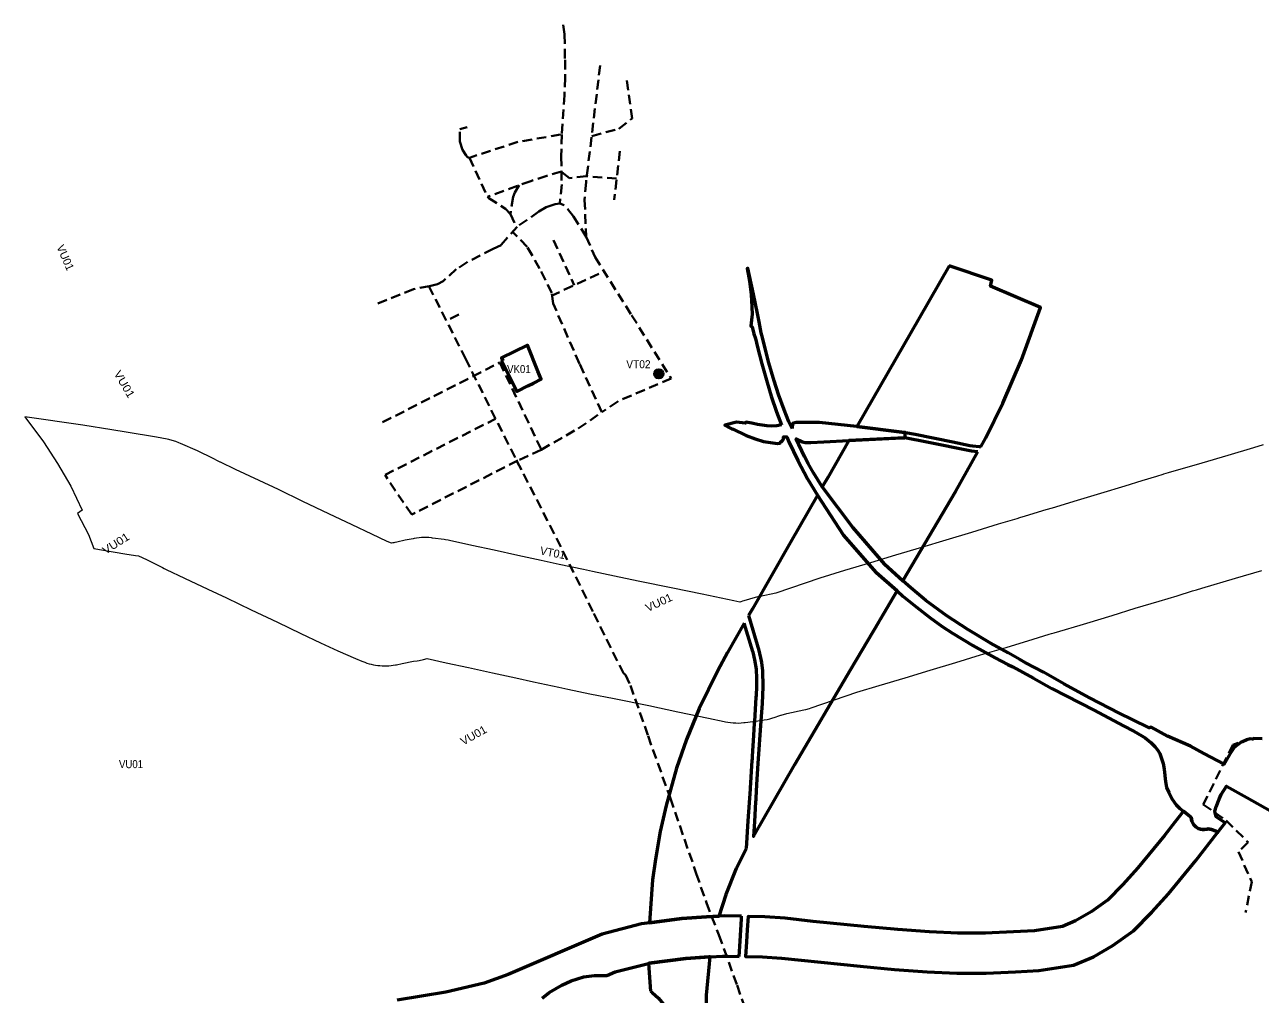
# Model space of a CAD drawing. Extents: x -650145 to -642675, y -1074338 to -1066724.
# Drawn here: x -649600 to -646512, y -1069147 to -1066724 of the extents above; entities that cross this region are included whole.
import ezdxf

# ---------------------------------------------------------------- set-up
doc = ezdxf.new("R2010")
doc.units = 0
doc.header["$LTSCALE"] = 8
doc.linetypes.add('MEDIUM_DASHED', pattern=[4.5, 3, -1.5])
for name, color, linetype in [('1', 7, 'Continuous'), ('17', 7, 'Continuous'), ('2', 7, 'Continuous')]:
    doc.layers.add(name, color=color, linetype=linetype)
for name, color, linetype, lineweight in [('12', 7, 'MEDIUM_DASHED', 40), ('15', 7, 'Continuous', 13), ('44', 7, 'Continuous', 53), ('45', 7, 'Continuous', 53)]:
    doc.layers.add(name, color=color, linetype=linetype, lineweight=lineweight)

msp = doc.modelspace()

# ---------------------------------------------------------------- hatches: boundary and pattern name
at = {"layer": '15'}
msp.add_hatch(color=256, dxfattribs=at).paths.add_polyline_path([(-648003.776, -1067596.576, 1), (-648027.301, -1067596.576, 1)])

# ---------------------------------------------------------------- linework, layer by layer
at = {"layer": '12'}
for p, q in [((-648112.923, -1067040.185), (-648126.71, -1067161.68)), ((-648278.693, -1067262.163), (-648226.9, -1067375.166)), ((-648165.273, -1067346.538), (-648282.098, -1067400.808)), ((-648515.199, -1067448.468), (-648546.557, -1067463.228))]:
    msp.add_line(p, q, dxfattribs=at)
for points in [[(-648254.111, -1066724.115), (-648250.825, -1066748.213), (-648249.73, -1066811.744), (-648248.971, -1066855.783), (-648251.033, -1066899.78), (-648258.055, -1066998.612), (-648259.37, -1067053.379), (-648258.055, -1067123.482), (-648262.874, -1067170.801), (-648274.266, -1067172.334), (-648297.049, -1067180.221), (-648315.013, -1067191.174), (-648369.562, -1067228.854), (-648409.651, -1067274.641), (-648429.367, -1067284.499), (-648494.475, -1067317.053), (-648521.596, -1067335.324), (-648554.018, -1067364.678), (-648568.696, -1067372.565), (-648588.85, -1067377.165), (-648628.502, -1067385.052), (-648726.865, -1067424.267)], [(-648161.945, -1066826.336), (-648197.181, -1067117.94), (-648200.826, -1067161.68), (-648196.766, -1067253.967), (-648228.816, -1067203.221), (-648251.518, -1067175.177), (-648262.874, -1067170.801)], [(-648182.601, -1067002.513), (-648115.19, -1066984.032), (-648082.101, -1066958.613), (-648096.04, -1066857.23)], [(-648488.5, -1067056.457), (-648493.497, -1067055.091), (-648496.863, -1067051.153), (-648505.895, -1067036.526), (-648512.776, -1067015.949), (-648512.582, -1066985.375), (-648494.033, -1066979.937)], [(-648261.097, -1066998.621), (-648367.277, -1067016.878), (-648488.5, -1067056.457), (-648443.711, -1067154.017)], [(-648258.664, -1067091.005), (-648295.035, -1067101.44), (-648334.906, -1067114.73), (-648443.711, -1067154.017), (-648440.351, -1067157.668), (-648398.143, -1067183.811), (-648386.313, -1067197.539), (-648370.813, -1067230.283)], [(-648120.689, -1067108.619), (-648196.172, -1067102.839), (-648238.811, -1067107.157), (-648258.654, -1067091.57)], [(-648364.124, -1067125.28), (-648375.197, -1067142.997), (-648379.372, -1067154.48), (-648386.313, -1067197.539)], [(-648196.766, -1067253.967), (-648174.431, -1067304.992), (-648083.383, -1067449.946), (-647984.432, -1067607.856), (-648117.975, -1067665.279), (-648157.356, -1067692.42), (-648213.545, -1067571.236), (-648279.612, -1067420.693), (-648282.899, -1067394.398), (-648313.139, -1067332.931), (-648344.694, -1067279.025), (-648380.675, -1067241.546)], [(-648589.741, -1067377.342), (-648498.624, -1067558.559), (-648369.855, -1067814.661), (-648270.948, -1068007.281), (-648177.599, -1068195.293), (-648103.97, -1068344.741), (-648098.419, -1068348.539), (-648086.184, -1068375.018), (-648042.175, -1068501.421), (-647986.295, -1068657.442), (-647921.652, -1068844.799), (-647896.268, -1068918.371), (-647865.117, -1068998.629), (-647819.537, -1069124.409), (-647801.818, -1069175.256)], [(-648705.527, -1067717.518), (-648412.884, -1067568.459), (-648309.025, -1067786), (-648368.053, -1067813.183), (-648633.004, -1067948.289), (-648699.635, -1067849.093), (-648423.205, -1067708.555)], [(-648309.025, -1067786), (-648216.797, -1067733.386), (-648157.356, -1067692.42)], [(-646567.712, -1068518.211), (-646580.293, -1068523.244), (-646654.473, -1068672.619), (-646597.568, -1068712.249), (-646542.696, -1068767.122), (-646566.575, -1068791.001), (-646533.55, -1068865.689), (-646548.767, -1068942.794)]]:
    msp.add_lwpolyline(points, dxfattribs=at)
at = {"layer": '15'}
for points in [[(-649382.683, -1067736.41), (-649454.621, -1067724.642), (-649600.146, -1067704.069)], [(-649600.146, -1067704.069), (-649553.44, -1067766.28), (-649518.25, -1067820.92), (-649485.13, -1067877.09), (-649456.24, -1067937.25), (-649467.89, -1067945.1), (-649440.52, -1067998.08), (-649427.146, -1068033.129), (-649350.073, -1068045.91)], [(-646504.961, -1067774.022), (-646529.365, -1067781.499), (-646593.13, -1067800.524), (-646658.06, -1067819.479), (-646742.053, -1067843.994), (-646753.887, -1067847.445), (-646755.382, -1067847.819), (-646771.25, -1067852.794), (-646807.854, -1067864.206), (-646850.892, -1067877.156), (-646911.586, -1067895.218), (-646969.855, -1067913.144), (-647032.093, -1067931.929), (-647048.173, -1067936.726), (-647099.576, -1067952.077), (-647114.132, -1067956.487), (-647120.451, -1067958.402), (-647126.241, -1067960.149), (-647166.751, -1067972.422), (-647233.528, -1067992.581), (-647298.314, -1068011.911), (-647358.997, -1068030.632), (-647423.612, -1068049.375), (-647486.376, -1068068.781), (-647550.936, -1068088.002), (-647612.779, -1068106.747), (-647722.769, -1068144.312), (-647762.416, -1068152.578), (-647765.408, -1068153.202), (-647771.336, -1068154.692), (-647774.267, -1068155.557), (-647802.757, -1068163.967), (-647805.815, -1068164.87), (-647810.703, -1068166.542), (-647812.571, -1068166.788), (-647827.9, -1068163.347), (-647906.909, -1068147.095), (-647980.144, -1068131.782), (-648067.22, -1068114.186), (-648126.418, -1068101.998), (-648181.06, -1068090.497), (-648203.256, -1068085.824), (-648264.087, -1068072.869), (-648309.141, -1068062.702), (-648367.602, -1068050.464), (-648426.568, -1068037.47), (-648482.748, -1068025.289), (-648538.58, -1068012.914), (-648541.779, -1068012.205), (-648548.234, -1068011.067), (-648551.482, -1068010.64), (-648580.682, -1068006.8), (-648583.733, -1068006.399), (-648589.862, -1068005.847), (-648596.008, -1068005.548), (-648602.162, -1068005.5), (-648608.312, -1068005.705), (-648614.449, -1068006.163), (-648620.561, -1068006.871), (-648626.64, -1068007.83), (-648629.657, -1068008.433), (-648649.671, -1068012.436), (-648670.491, -1068016.914), (-648675.031, -1068017.89), (-648677.625, -1068018.618), (-648680.26, -1068018.992), (-648683.7, -1068019.718), (-648693.991, -1068015.264), (-648732.758, -1067996.958), (-648781.439, -1067974.125), (-648839.635, -1067946.226), (-648905.118, -1067915.461), (-648966.216, -1067885.853), (-649013.828, -1067863.231), (-649073.136, -1067835.331), (-649111.1, -1067817.381), (-649111.919, -1067816.904), (-649116.61, -1067814.593), (-649129.493, -1067808.246), (-649168.436, -1067789.027), (-649210.538, -1067770.325), (-649214.568, -1067768.535), (-649222.823, -1067765.435), (-649231.246, -1067762.826), (-649239.808, -1067760.715), (-649244.144, -1067759.913), (-649270.928, -1067754.958), (-649346.551, -1067742.368), (-649382.683, -1067736.41)], [(-649350.073, -1068045.91), (-649322.852, -1068050.442), (-649316.134, -1068051.685), (-649295.764, -1068060.733), (-649262.167, -1068077.314), (-649255.583, -1068080.557), (-649251.7, -1068082.747), (-649246.836, -1068085.047), (-649201.104, -1068106.669), (-649142.052, -1068134.449), (-649096.004, -1068156.327), (-649034.322, -1068186.219), (-648968.265, -1068217.254), (-648909.981, -1068245.195), (-648860.502, -1068268.402), (-648817.649, -1068288.636), (-648773.793, -1068307.617), (-648757.876, -1068314.337), (-648755.322, -1068315.416), (-648750.136, -1068317.382), (-648744.882, -1068319.156), (-648739.566, -1068320.735), (-648734.195, -1068322.115), (-648728.777, -1068323.297), (-648723.319, -1068324.277), (-648717.828, -1068325.055), (-648712.312, -1068325.63), (-648706.779, -1068326), (-648701.236, -1068326.166), (-648695.69, -1068326.126), (-648690.15, -1068325.882), (-648684.623, -1068325.433), (-648679.116, -1068324.78), (-648673.637, -1068323.924), (-648670.915, -1068323.395), (-648657.024, -1068320.696), (-648628.18, -1068314.608), (-648619.413, -1068313.366), (-648614.155, -1068312.621), (-648603.771, -1068310.391), (-648594.694, -1068307.758), (-648546.992, -1068318.331), (-648490.632, -1068330.55)], [(-648127.18, -1068408.134), (-648040.556, -1068425.638), (-647967.831, -1068440.845), (-647890.98, -1068456.653), (-647852.243, -1068465.348), (-647849.022, -1068466.071), (-647842.522, -1068467.232), (-647835.978, -1068468.107), (-647829.402, -1068468.692), (-647822.806, -1068468.988), (-647816.203, -1068468.993), (-647809.607, -1068468.707), (-647803.03, -1068468.132), (-647799.757, -1068467.7), (-647755.597, -1068461.87), (-647751.962, -1068461.39), (-647744.747, -1068460.076), (-647737.604, -1068458.41), (-647730.552, -1068456.398), (-647727.079, -1068455.221), (-647712.829, -1068450.391), (-647710.163, -1068449.487), (-647709.521, -1068449.242), (-647695.198, -1068445.014), (-647652.454, -1068436.102), (-647647.917, -1068435.156), (-647638.976, -1068432.708), (-647634.59, -1068431.21), (-647520.761, -1068392.333), (-647464.624, -1068375.318), (-647399.264, -1068355.859), (-647337.508, -1068336.765), (-647272.983, -1068318.048), (-647211.206, -1068298.989), (-647147.292, -1068279.919), (-647079.909, -1068259.578), (-647039.419, -1068247.311), (-647033.609, -1068245.558), (-647027.128, -1068243.593), (-647013.164, -1068239.363), (-646962.367, -1068224.194), (-646945.867, -1068219.271), (-646882.405, -1068200.116), (-646824.694, -1068182.362), (-646764.888, -1068164.564), (-646719.986, -1068151.054), (-646681.73, -1068139.126), (-646671.337, -1068135.868), (-646658.027, -1068131.986), (-646574, -1068107.461), (-646508.21, -1068088.256)], [(-648490.632, -1068330.55), (-648430.618, -1068343.776), (-648372.899, -1068355.858), (-648328.353, -1068365.911), (-648265.404, -1068379.316), (-648242.86, -1068384.063), (-648187.562, -1068395.702), (-648127.18, -1068408.134)]]:
    msp.add_lwpolyline(points, dxfattribs=at)
at = {"layer": '15', "lineweight": 35}
msp.add_circle((-648015.538, -1067596.576), 11.762, dxfattribs=at)
at = {"layer": '44'}
msp.add_line((-648038.596, -1068968.281), (-647958.168, -1068957.73), dxfattribs=at)
for points in [[(-647289.924, -1067326.309), (-647364.024, -1067455.561), (-647520.145, -1067727.879), (-647408.2, -1067742.37), (-647398.74, -1067743.15)], [(-647210.537, -1067778.594), (-647198.088, -1067756.5), (-647155.592, -1067670.17), (-647108.971, -1067561.55), (-647061.252, -1067430.908), (-647185.93, -1067377.38), (-647183.09, -1067362.16), (-647289.924, -1067326.309)], [(-647398.74, -1067743.15), (-647374.55, -1067747.34), (-647280.78, -1067766.44), (-647237.91, -1067775.18), (-647231.17, -1067776.55), (-647213.92, -1067778.26), (-647210.537, -1067778.594)], [(-647400.63, -1067756.19), (-647540.208, -1067762.876), (-647593.267, -1067855.425), (-647606.818, -1067879.061)], [(-647217.611, -1067791.149), (-647233.83, -1067789.69), (-647345.11, -1067767.28), (-647400.63, -1067756.19)], [(-647405.026, -1068113.904), (-647273.297, -1067889.981), (-647217.611, -1067791.149)], [(-647464.94, -1068215.752), (-647461.188, -1068209.373), (-647419.713, -1068138.871), (-647472.338, -1068093.096), (-647553.628, -1067999.427), (-647618.773, -1067899.914), (-647685.819, -1068016.861)], [(-647606.818, -1067879.061), (-647530.038, -1067980.839), (-647451.024, -1068071.886), (-647405.026, -1068113.904)], [(-647685.819, -1068016.861), (-647781.346, -1068183.485), (-647791.055, -1068200.507)], [(-647791.055, -1068200.507), (-647765.22, -1068287.94), (-647759.412, -1068313.436)], [(-647801.797, -1068219.34), (-647843.6, -1068292.629), (-647868.214, -1068337.803), (-647914.339, -1068432.512), (-647946.187, -1068510.254), (-647971.074, -1068581.98), (-647997.27, -1068674.747), (-648011.775, -1068739.718), (-648023.914, -1068809.332), (-648030.73, -1068861.213), (-648038.596, -1068968.281)], [(-647771.413, -1068334.626), (-647774.94, -1068311.47), (-647779.55, -1068292.23), (-647780.07, -1068290.53), (-647801.797, -1068219.34)], [(-647768.02, -1068570.36), (-647770.94, -1068622.47), (-647772.85, -1068656.41), (-647773.08, -1068660.57), (-647773.4, -1068665.71), (-647776.5, -1068714.8), (-647778.95, -1068752.433), (-647675.054, -1068572.919), (-647535.844, -1068336.279), (-647464.94, -1068215.752)], [(-647759.412, -1068313.436), (-647758.45, -1068317.66), (-647756.09, -1068337.61), (-647754.99, -1068378.21), (-647757.41, -1068419.98), (-647760.22, -1068463.96), (-647768.02, -1068570.36)], [(-647796.173, -1068782.191), (-647791.77, -1068713.23), (-647786.47, -1068634.37), (-647786.32, -1068632.19), (-647781.85, -1068562.97), (-647781.55, -1068558.38), (-647781.13, -1068551.88), (-647778.24, -1068499.95), (-647775.82, -1068469.74), (-647775.52, -1068464.97), (-647771.74, -1068404.5), (-647771.47, -1068400.07), (-647770.12, -1068377.5), (-647769.92, -1068352.1), (-647770.81, -1068340.29), (-647771.05, -1068337.01), (-647771.413, -1068334.626)], [(-647846.989, -1068896.545), (-647820.883, -1068832.117), (-647797.632, -1068784.713), (-647796.173, -1068782.191)], [(-647958.168, -1068957.73), (-647895.901, -1068953.392), (-647864.531, -1068951.823), (-647847.197, -1068897.199), (-647847.034, -1068896.687), (-647846.989, -1068896.545)], [(-647948.18, -1069057.276), (-648039.666, -1069069.279), (-648040.705, -1069069.548), (-648036.291, -1069139.458)], [(-647886.615, -1069053.052), (-647889.927, -1069053.218), (-647948.18, -1069057.276)], [(-647893.553, -1069279.017), (-647896.67, -1069213.573), (-647896.362, -1069149.171), (-647886.615, -1069053.052)], [(-648036.291, -1069139.458), (-648031.92, -1069142.67), (-648016.36, -1069156.54), (-647993.8, -1069184.11)]]:
    msp.add_lwpolyline(points, dxfattribs=at)
at = {"layer": '45'}
for points in [[(-647681.91, -1067732.74), (-647690.09, -1067716.05), (-647702.04, -1067686.86), (-647715.92, -1067648.12), (-647727.37, -1067614.33), (-647740.49, -1067568.67), (-647751.41, -1067526.58), (-647756.55, -1067505.32), (-647759.16, -1067494.01), (-647764.89, -1067466.64), (-647768.5, -1067446.04), (-647778.78, -1067397.1), (-647792.52, -1067332.74), (-647794.54, -1067333.14), (-647788.77, -1067365.03), (-647784.55, -1067398.01), (-647783.21, -1067429.237)], [(-647783.21, -1067429.237), (-647782.39, -1067448.34), (-647782.5, -1067455.11), (-647784.36, -1067469.6), (-647785.64, -1067477.02), (-647781.85, -1067479.19), (-647777.55, -1067496.95), (-647773.96, -1067508.48), (-647768.5, -1067529.75), (-647758.25, -1067571.79)], [(-647758.25, -1067571.79), (-647744.61, -1067617.96), (-647734.63, -1067652.57), (-647721.05, -1067691.73), (-647708.71, -1067723.99)], [(-647821.02, -1067717.33), (-647850.45, -1067724.77), (-647838.18, -1067731.62), (-647832.56, -1067734.22), (-647829.49, -1067734.58)], [(-647829.49, -1067734.58), (-647796.87, -1067750.25), (-647774.54, -1067758.68), (-647753.53, -1067765.58), (-647718.54, -1067770.6), (-647712.01, -1067769.63), (-647712.26, -1067767.28), (-647709.834, -1067766.324), (-647707.985, -1067765.133), (-647706.723, -1067763.999), (-647705.29, -1067762.21), (-647704.447, -1067760.707), (-647703.675, -1067758.576), (-647703.315, -1067756.406), (-647703.4, -1067753.8), (-647695.71, -1067753.9), (-647690.19, -1067766.37), (-647668.13, -1067812.76), (-647643.83, -1067859.13), (-647618.773, -1067899.914), (-647553.628, -1067999.427), (-647472.338, -1068093.096), (-647419.713, -1068138.871), (-647405.71, -1068151.74), (-647372.38, -1068179.01), (-647337.74, -1068205.67), (-647307.39, -1068227.44), (-647281.64, -1068244.34), (-647230.83, -1068274.93), (-647174.56, -1068306.35), (-647142.788, -1068322.462), (-647130.29, -1068328.8), (-647079.16, -1068357.01), (-647032.91, -1068382.51), (-646997.06, -1068401.37), (-646927.06, -1068436.66), (-646854.18, -1068475.8), (-646828.2, -1068489.61), (-646807.82, -1068501.17), (-646799.79, -1068506.39), (-646785.34, -1068517.77), (-646775.44, -1068527.74), (-646768.95, -1068535.8), (-646763.1, -1068545.18), (-646754.92, -1068569.81), (-646752.59, -1068584.55), (-646749.35, -1068615.18), (-646746.32, -1068630.23)], [(-647708.71, -1067723.99), (-647720.45, -1067726.49), (-647732.71, -1067727.02), (-647745.41, -1067726.6), (-647768.53, -1067722.82), (-647783.13, -1067719.68), (-647798.17, -1067717.58), (-647798.5, -1067719.67), (-647821.02, -1067717.33)], [(-646653.21, -1068545.58), (-646653.21, -1068545.58), (-646686.84, -1068526.89), (-646743.69, -1068501.76), (-646785.05, -1068479.12), (-646789.49, -1068481.31), (-646832.29, -1068460.04), (-646864.48, -1068444.64), (-646938.95, -1068405.8), (-647002.71, -1068371.09), (-647053.75, -1068342.11), (-647099.2, -1068318.27), (-647112.813, -1068310.564), (-647142.41, -1068293.81), (-647186.26, -1068269.45), (-647243.39, -1068235.26), (-647295.47, -1068201.09), (-647347.74, -1068162.54), (-647353.81, -1068157.67), (-647385.13, -1068131.51), (-647405.026, -1068113.904), (-647451.024, -1068071.886), (-647530.038, -1067980.839), (-647606.818, -1067879.061), (-647628.396, -1067844.048), (-647642.29, -1067820.76), (-647650.8, -1067803.28), (-647672.05, -1067758.98), (-647656.469, -1067766.309), (-647649.22, -1067768.38), (-647635.758, -1067768.38), (-647602.885, -1067766.486), (-647540.208, -1067762.876), (-647423.683, -1067757.294), (-647400.63, -1067756.19), (-647398.74, -1067743.15), (-647408.2, -1067742.37), (-647520.145, -1067727.879), (-647614, -1067718), (-647617.443, -1067718), (-647643, -1067718), (-647672, -1067718), (-647680.804, -1067720.745), (-647681.91, -1067732.74)], [(-646507.4, -1068508.45), (-646528.18, -1068507.58), (-646531.9, -1068509.25), (-646537.71, -1068508.16), (-646545.57, -1068511.42), (-646556.22, -1068515.84), (-646559.72, -1068517.29), (-646569.61, -1068524.1), (-646577.07, -1068530.2), (-646587.28, -1068545.28), (-646599.75, -1068566.49), (-646602.21, -1068571.5), (-646653.21, -1068545.58), (-646653.21, -1068545.58)], [(-646746.32, -1068630.23), (-646740.91, -1068642.34), (-646732.25, -1068659.06), (-646722.6, -1068673.11)], [(-646722.6, -1068673.11), (-646712.93, -1068683), (-646684.7, -1068704.95), (-646682.98, -1068714.07), (-646680.88, -1068719.28), (-646678.08, -1068723.7), (-646673.16, -1068728.69), (-646667.17, -1068732.38), (-646661.5, -1068734.35), (-646656.47, -1068735.13), (-646651.21, -1068734.99), (-646645.18, -1068733.91), (-646642.04, -1068733.74), (-646634.37, -1068735.27), (-646622.62, -1068739.32), (-646617.991, -1068741.503), (-646599.51, -1068718.755), (-646622.01, -1068703.3), (-646625.35, -1068689.7), (-646622.68, -1068678.75), (-646615.19, -1068659.11), (-646609.7, -1068647.84), (-646596.28, -1068626.52), (-646545.73, -1068654.81), (-646486.23, -1068688.54)], [(-648038.759, -1068968.54), (-648038.746, -1068968.301), (-648058.764, -1068970.927), (-648156.739, -1068996.273), (-648392.002, -1069097.554), (-648451.865, -1069119.456), (-648547.243, -1069141.81), (-648668.959, -1069161.838)], [(-647864.531, -1068951.823), (-647895.901, -1068953.392), (-647958.168, -1068957.73), (-648038.596, -1068968.281), (-648038.759, -1068968.54)], [(-647808.28, -1068952.066), (-647850.043, -1068951.098), (-647864.531, -1068951.823)], [(-647814.401, -1069052.246), (-647812.34, -1069014.54), (-647808.67, -1068958.06), (-647808.28, -1068952.066)], [(-648306.83, -1069156.57), (-648289.25, -1069142.79), (-648257.5, -1069124.41), (-648234.22, -1069113.6), (-648202.46, -1069103.3), (-648175.65, -1069099.64), (-648144.866, -1069099.987), (-648124.327, -1069091.181), (-648040.705, -1069069.547)], [(-648040.705, -1069069.547), (-648039.666, -1069069.279), (-647948.18, -1069057.276), (-647886.615, -1069053.052), (-647856.541, -1069051.548), (-647848.615, -1069051.679), (-647842.888, -1069051.774), (-647814.401, -1069052.246)]]:
    msp.add_lwpolyline(points, dxfattribs=at)
for points in [[(-648405.41, -1067563.84), (-648408.002, -1067565.219), (-648369.949, -1067640.851), (-648342.697, -1067626.806), (-648328.54, -1067619.51), (-648309.522, -1067609.713), (-648317.43, -1067590), (-648343.41, -1067524.81), (-648408.26, -1067556.58)], [(-646934.465, -1068940.759), (-646973.61, -1068963.135), (-647006.63, -1068977.08), (-647076.422, -1068988.18), (-647128.674, -1068991.167), (-647199.672, -1068994.255), (-647268.348, -1068994.255), (-647338.816, -1068991.19), (-647417.895, -1068984.986), (-647502.412, -1068977.157), (-647629.424, -1068964.608), (-647699.561, -1068956.635), (-647749.978, -1068953.416), (-647792.01, -1068952.442), (-647794.21, -1068986.12), (-647796.13, -1069015.57), (-647798.631, -1069052.508), (-647756.441, -1069053.207), (-647708.401, -1069056.275), (-647511.94, -1069076.703), (-647426.417, -1069084.624), (-647344.902, -1069091.02), (-647270.522, -1069094.255), (-647197.498, -1069094.255), (-647123.648, -1069091.043), (-647065.688, -1069087.73), (-646978.92, -1069073.93), (-646929.186, -1069052.925), (-646880.163, -1069024.903), (-646829.104, -1068987.917), (-646782.784, -1068941.581), (-646741.85, -1068895.719), (-646673.05, -1068812.491), (-646618.655, -1068742.359), (-646617.991, -1068741.503), (-646622.62, -1068739.32), (-646634.37, -1068735.27), (-646642.04, -1068733.74), (-646645.18, -1068733.91), (-646651.21, -1068734.99), (-646656.47, -1068735.13), (-646661.5, -1068734.35), (-646667.17, -1068732.38), (-646673.16, -1068728.69), (-646678.08, -1068723.7), (-646680.88, -1068719.28), (-646682.98, -1068714.07), (-646684.7, -1068704.95), (-646704.316, -1068689.698), (-646725.374, -1068716.786), (-646751.116, -1068749.975), (-646817.718, -1068830.545), (-646855.506, -1068872.883), (-646894.206, -1068911.595)]]:
    msp.add_lwpolyline(points, close=True, dxfattribs=at)

# ---------------------------------------------------------------- texts
at = {"layer": '1', "width": 0.9}
msp.add_text('VK01', height=20, dxfattribs=at).set_placement((-648394.54, -1067594.58))
at = {"layer": '17', "width": 0.95}
msp.add_text('VT02', height=20, dxfattribs=at).set_placement((-648096.61, -1067582.461))
at = {"layer": '17'}
msp.add_text('VT01', height=20, rotation=348.908, dxfattribs=at).set_placement((-648313.65, -1068047.434))
at = {"layer": '2'}
msp.add_text('VU01', height=20, rotation=293.833, dxfattribs=at).set_placement((-649521.27, -1067279.43))
for rotation, width, p in [(300.389, 1.1, (-649378.291, -1067595.604)), (32.546, 1.1, (-649398.133, -1068048.567)), (25.207, 1.05, (-648042.803, -1068191.925)), (29.08, 1.05, (-648504.265, -1068525.557)), (0.068, 0.9, (-649364.51, -1068581.837))]:
    msp.add_text('VU01', height=20, rotation=rotation, dxfattribs=dict(at, width=width)).set_placement(p)

doc.saveas('drawing.dxf')
